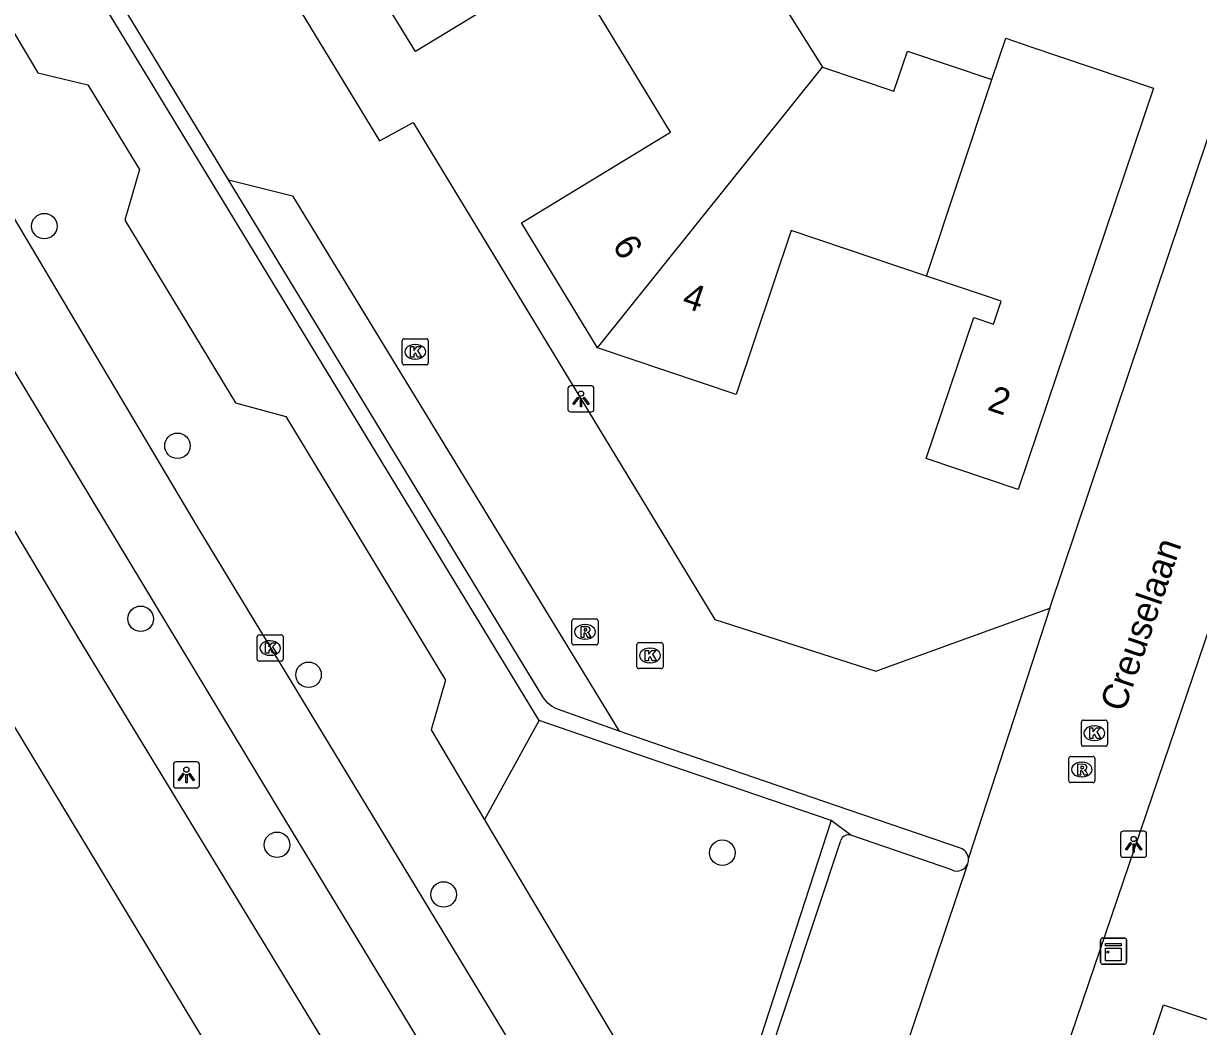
# Model space of a CAD drawing. Extents: x 157767 to 159171, y 387842 to 389425.
# Drawn here: x 158155.67 to 158200.72, y 388302.87 to 388341.31 of the extents above; entities that cross this region are included whole.
import ezdxf

# ---------------------------------------------------------------- set-up
doc = ezdxf.new("R2010")
doc.units = 0
for name, color, linetype in [('IMGEO_Boom', 7, 'Continuous'), ('IMGEO_Fietspad_gesloten', 7, 'Continuous'), ('IMGEO_Groenvoorziening', 7, 'Continuous'), ('IMGEO_Kast', 7, 'Continuous'), ('IMGEO_Kolk', 7, 'Continuous'), ('IMGEO_Lichtpunt', 7, 'Continuous'), ('IMGEO_Muur', 7, 'Continuous'), ('IMGEO_Openbare_ruimte_label', 7, 'Continuous'), ('IMGEO_Pand', 7, 'Continuous'), ('IMGEO_Pand_nummerreeks', 7, 'Continuous'), ('IMGEO_Rijbaan_lokaal_open', 7, 'Continuous'), ('IMGEO_Rijbaan_regionaal_gesloten', 7, 'Continuous'), ('IMGEO_Rioolput', 7, 'Continuous'), ('IMGEO_Voetpad_open', 7, 'Continuous')]:
    doc.layers.add(name, color=color, linetype=linetype)

msp = doc.modelspace()

# ---------------------------------------------------------------- linework, layer by layer
at = {"layer": 'IMGEO_Boom'}
for centre in [(158156.47, 388333.544), (158161.572, 388325.124), (158160.162, 388318.494), (158166.599, 388316.349), (158165.391, 388309.834), (158182.464, 388309.529), (158171.777, 388307.929)]:
    msp.add_circle(centre, 0.489, dxfattribs=at)
at = {"layer": 'IMGEO_Fietspad_gesloten'}
for points in [[(158134.936, 388368.569), (158152.031, 388339.346), (158162.359, 388321.986), (158175.742, 388299.912), (158188.418, 388279.263), (158195.13, 388268.765)], [(158178.868, 388289.086), (158165.181, 388311.658), (158153.286, 388331.356), (158142.759, 388349.282), (158132.45, 388366.885)]]:
    msp.add_lwpolyline(points, dxfattribs=at)
at = {"layer": 'IMGEO_Groenvoorziening'}
for points in [[(158133.376, 388377.573), (158139.588, 388367.158), (158141.543, 388366.666), (158143.57, 388363.424), (158142.99, 388361.495), (158145.126, 388357.922), (158147.067, 388357.45), (158149.128, 388354.196), (158148.513, 388352.268), (158150.628, 388348.658), (158152.625, 388348.163), (158154.628, 388344.956), (158154.075, 388343.02), (158156.218, 388339.413), (158158.137, 388338.952), (158160.119, 388335.714), (158159.551, 388333.769), (158163.802, 388326.774), (158165.73, 388326.242), (158171.855, 388316.141), (158171.296, 388314.237), (158173.351, 388310.787)], [(158173.351, 388310.787), (158175.446, 388314.592)], [(158173.351, 388310.787), (158183.658, 388293.483), (158185.543, 388292.972), (158189.658, 388286.335), (158189.095, 388284.416), (158195.332, 388273.955), (158197.254, 388273.407), (158198.647, 388271.084)]]:
    msp.add_lwpolyline(points, dxfattribs=at)
at = {"layer": 'IMGEO_Kast'}
for p, q in [((158197.037, 388306.26), (158197.878, 388306.26)), ((158197.878, 388306.26), (158197.037, 388306.26)), ((158196.962, 388305.335), (158196.962, 388306.176)), ((158196.962, 388306.176), (158196.962, 388305.335)), ((158197.962, 388306.185), (158197.962, 388305.344)), ((158197.962, 388305.344), (158197.962, 388306.185)), ((158197.887, 388305.26), (158197.046, 388305.26)), ((158197.046, 388305.26), (158197.887, 388305.26))]:
    msp.add_line(p, q, dxfattribs=at)
for points in [[(158197.157, 388306.05), (158197.757, 388306.05), (158197.757, 388305.965), (158197.157, 388305.965), (158197.157, 388306.05)], [(158197.157, 388305.875), (158197.757, 388305.875), (158197.757, 388305.386), (158197.157, 388305.386), (158197.157, 388305.875)]]:
    msp.add_lwpolyline(points, dxfattribs=at)
msp.add_circle((158197.241, 388305.724), 0.0377, dxfattribs=at)
for centre, start, end in [((158197.04, 388306.182), 92.4484, 184.2845), ((158197.04, 388306.182), 92.4484, 184.2845), ((158197.884, 388306.182), 2.4484, 94.2845), ((158197.884, 388306.182), 2.4484, 94.2845), ((158197.04, 388305.338), 182.4484, 274.2845), ((158197.04, 388305.338), 182.4484, 274.2845), ((158197.884, 388305.338), 272.4484, 4.2845), ((158197.884, 388305.338), 272.4484, 4.2845)]:
    msp.add_arc(centre, 0.0779, start, end, dxfattribs=at)
at = {"layer": 'IMGEO_Kolk'}
for p, q in [((158170.263, 388329.225), (158171.115, 388329.225)), ((158170.188, 388328.299), (158170.188, 388329.151)), ((158170.676, 388329.005), (158170.701, 388329.005)), ((158171.189, 388329.151), (158171.189, 388328.299)), ((158170.699, 388328.445), (158170.674, 388328.445)), ((158171.115, 388328.225), (158170.263, 388328.225)), ((158164.626, 388316.948), (158164.626, 388317.8)), ((158164.701, 388317.874), (158165.553, 388317.874)), ((158165.114, 388317.654), (158165.139, 388317.654)), ((158165.627, 388317.8), (158165.627, 388316.948)), ((158179.19, 388316.658), (158179.19, 388317.51)), ((158179.265, 388317.584), (158180.117, 388317.584)), ((158180.191, 388317.51), (158180.191, 388316.658)), ((158165.137, 388317.094), (158165.112, 388317.094)), ((158179.678, 388317.364), (158179.703, 388317.364)), ((158165.553, 388316.874), (158164.701, 388316.874)), ((158180.117, 388316.584), (158179.265, 388316.584)), ((158179.701, 388316.804), (158179.676, 388316.804)), ((158196.229, 388313.684), (158196.229, 388314.536)), ((158196.304, 388314.61), (158197.156, 388314.61)), ((158196.717, 388314.39), (158196.742, 388314.39)), ((158197.23, 388314.536), (158197.23, 388313.684)), ((158197.156, 388313.61), (158196.304, 388313.61)), ((158196.74, 388313.83), (158196.715, 388313.83))]:
    msp.add_line(p, q, dxfattribs=at)
for points in [[(158170.263, 388329.225), (158171.115, 388329.225)], [(158170.188, 388328.299), (158170.188, 388329.151)], [(158170.509, 388328.925), (158170.632, 388328.925), (158170.632, 388328.774), (158170.762, 388328.925), (158170.926, 388328.925), (158170.78, 388328.774), (158170.933, 388328.525), (158170.781, 388328.525), (158170.696, 388328.689), (158170.632, 388328.622), (158170.632, 388328.525), (158170.509, 388328.525), (158170.509, 388328.925)], [(158171.189, 388329.151), (158171.189, 388328.299)], [(158171.115, 388328.225), (158170.263, 388328.225)], [(158164.626, 388316.948), (158164.626, 388317.8)], [(158164.701, 388317.874), (158165.553, 388317.874)], [(158164.947, 388317.574), (158165.07, 388317.574), (158165.07, 388317.423), (158165.2, 388317.574), (158165.364, 388317.574), (158165.218, 388317.423), (158165.371, 388317.174), (158165.219, 388317.174), (158165.134, 388317.338), (158165.07, 388317.271), (158165.07, 388317.174), (158164.947, 388317.174), (158164.947, 388317.574)], [(158165.627, 388317.8), (158165.627, 388316.948)], [(158179.19, 388316.658), (158179.19, 388317.51)], [(158179.265, 388317.584), (158180.117, 388317.584)], [(158180.191, 388317.51), (158180.191, 388316.658)], [(158179.511, 388317.284), (158179.634, 388317.284), (158179.634, 388317.133), (158179.764, 388317.284), (158179.928, 388317.284), (158179.782, 388317.133), (158179.935, 388316.884), (158179.783, 388316.884), (158179.698, 388317.048), (158179.634, 388316.981), (158179.634, 388316.884), (158179.511, 388316.884), (158179.511, 388317.284)], [(158165.553, 388316.874), (158164.701, 388316.874)], [(158180.117, 388316.584), (158179.265, 388316.584)], [(158196.229, 388313.684), (158196.229, 388314.536)], [(158196.304, 388314.61), (158197.156, 388314.61)], [(158197.23, 388314.536), (158197.23, 388313.684)], [(158196.55, 388314.31), (158196.673, 388314.31), (158196.673, 388314.159), (158196.803, 388314.31), (158196.967, 388314.31), (158196.821, 388314.159), (158196.974, 388313.91), (158196.822, 388313.91), (158196.737, 388314.074), (158196.673, 388314.007), (158196.673, 388313.91), (158196.55, 388313.91), (158196.55, 388314.31)], [(158197.156, 388313.61), (158196.304, 388313.61)]]:
    msp.add_lwpolyline(points, dxfattribs=at)
for centre, start, end in [((158170.265, 388329.149), 91.552, 178.448), ((158170.265, 388329.149), 91.552, 178.448), ((158171.113, 388329.149), 1.552, 88.448), ((158171.113, 388329.149), 1.552, 88.448), ((158170.265, 388328.301), 181.552, 268.448), ((158170.265, 388328.301), 181.552, 268.448), ((158171.113, 388328.301), 271.552, 358.448), ((158171.113, 388328.301), 271.552, 358.448), ((158164.703, 388317.798), 91.552, 178.448), ((158164.703, 388317.798), 91.552, 178.448), ((158165.551, 388317.798), 1.552, 88.448), ((158165.551, 388317.798), 1.552, 88.448), ((158179.267, 388317.508), 91.552, 178.448), ((158179.267, 388317.508), 91.552, 178.448), ((158180.115, 388317.508), 1.552, 88.448), ((158180.115, 388317.508), 1.552, 88.448), ((158164.703, 388316.95), 181.552, 268.448), ((158164.703, 388316.95), 181.552, 268.448), ((158165.551, 388316.95), 271.552, 358.448), ((158165.551, 388316.95), 271.552, 358.448), ((158179.267, 388316.66), 181.552, 268.448), ((158179.267, 388316.66), 181.552, 268.448), ((158180.115, 388316.66), 271.552, 358.448), ((158180.115, 388316.66), 271.552, 358.448), ((158196.306, 388314.534), 91.552, 178.448), ((158196.306, 388314.534), 91.552, 178.448), ((158197.154, 388314.534), 1.552, 88.448), ((158197.154, 388314.534), 1.552, 88.448), ((158196.306, 388313.686), 181.552, 268.448), ((158196.306, 388313.686), 181.552, 268.448), ((158197.154, 388313.686), 271.552, 358.448), ((158197.154, 388313.686), 271.552, 358.448)]:
    msp.add_arc(centre, 0.0765, start, end, dxfattribs=at)
for centre, major_axis, ratio, start_param, end_param in [((158170.675, 388328.725), (-0.387, 0.002), 0.722429, 4.712389, 7.853982), ((158170.7, 388328.725), (-0.39, 0.002), 0.717154, 1.570796, 4.712389), ((158165.113, 388317.374), (-0.387, 0.002), 0.722429, 4.712389, 7.853982), ((158165.138, 388317.374), (-0.39, 0.002), 0.717154, 1.570796, 4.712389), ((158179.677, 388317.084), (-0.387, 0.002), 0.722429, 4.712389, 7.853982), ((158179.702, 388317.084), (-0.39, 0.002), 0.717154, 1.570796, 4.712389), ((158196.716, 388314.11), (-0.387, 0.002), 0.722429, 4.712389, 7.853982), ((158196.741, 388314.11), (-0.39, 0.002), 0.717154, 1.570796, 4.712389)]:
    msp.add_ellipse(centre, major_axis=major_axis, ratio=ratio, start_param=start_param, end_param=end_param, dxfattribs=at)
at = {"layer": 'IMGEO_Lichtpunt'}
for p, q in [((158177.448, 388327.422), (158176.64, 388327.422)), ((158177.448, 388327.422), (158176.64, 388327.422)), ((158176.546, 388327.327), (158176.546, 388326.52)), ((158176.546, 388327.327), (158176.546, 388326.52)), ((158177.542, 388326.52), (158177.542, 388327.327)), ((158177.542, 388326.52), (158177.542, 388327.327)), ((158176.64, 388326.426), (158177.448, 388326.426)), ((158176.64, 388326.426), (158177.448, 388326.426)), ((158162.318, 388313.01), (158161.51, 388313.01)), ((158162.318, 388313.01), (158161.51, 388313.01)), ((158161.416, 388312.915), (158161.416, 388312.108)), ((158161.416, 388312.915), (158161.416, 388312.108)), ((158162.412, 388312.108), (158162.412, 388312.915)), ((158162.412, 388312.108), (158162.412, 388312.915)), ((158161.51, 388312.014), (158162.318, 388312.014)), ((158161.51, 388312.014), (158162.318, 388312.014)), ((158198.635, 388310.352), (158197.827, 388310.352)), ((158198.635, 388310.352), (158197.827, 388310.352)), ((158197.733, 388310.257), (158197.733, 388309.45)), ((158197.733, 388310.257), (158197.733, 388309.45)), ((158198.729, 388309.45), (158198.729, 388310.257)), ((158198.729, 388309.45), (158198.729, 388310.257)), ((158197.827, 388309.356), (158198.635, 388309.356)), ((158197.827, 388309.356), (158198.635, 388309.356))]:
    msp.add_line(p, q, dxfattribs=at)
for points in [[(158176.92, 388326.991), (158176.959, 388326.963), (158176.771, 388326.701), (158176.733, 388326.728), (158176.92, 388326.991)], [(158177.022, 388326.943), (158177.069, 388326.943), (158177.069, 388326.621), (158177.022, 388326.621), (158177.022, 388326.943)], [(158177.132, 388326.963), (158177.17, 388326.99), (158177.357, 388326.728), (158177.318, 388326.7), (158177.132, 388326.963)], [(158161.79, 388312.579), (158161.829, 388312.551), (158161.641, 388312.289), (158161.603, 388312.316), (158161.79, 388312.579)], [(158161.892, 388312.531), (158161.939, 388312.531), (158161.939, 388312.209), (158161.892, 388312.209), (158161.892, 388312.531)], [(158162.002, 388312.551), (158162.04, 388312.578), (158162.227, 388312.316), (158162.188, 388312.288), (158162.002, 388312.551)], [(158198.107, 388309.921), (158198.146, 388309.893), (158197.958, 388309.631), (158197.92, 388309.658), (158198.107, 388309.921)], [(158198.209, 388309.873), (158198.256, 388309.873), (158198.256, 388309.551), (158198.209, 388309.551), (158198.209, 388309.873)], [(158198.319, 388309.893), (158198.357, 388309.92), (158198.544, 388309.658), (158198.505, 388309.63), (158198.319, 388309.893)]]:
    msp.add_lwpolyline(points, dxfattribs=at)
for centre in [(158177.045, 388327.125), (158161.915, 388312.713), (158198.232, 388310.055)]:
    msp.add_circle(centre, 0.0994, dxfattribs=at)
for centre, start, end in [((158176.64, 388327.327), 90, 180), ((158176.64, 388327.327), 90, 180), ((158177.448, 388327.327), 0, 90), ((158177.448, 388327.327), 0, 90), ((158176.64, 388326.52), 180, 270), ((158176.64, 388326.52), 180, 270), ((158177.448, 388326.52), 270, 0), ((158177.448, 388326.52), 270, 360), ((158161.51, 388312.915), 90, 180), ((158161.51, 388312.915), 90, 180), ((158162.318, 388312.915), 0, 90), ((158162.318, 388312.915), 0, 90), ((158161.51, 388312.108), 180, 270), ((158161.51, 388312.108), 180, 270), ((158162.318, 388312.108), 270, 0), ((158162.318, 388312.108), 270, 360), ((158197.827, 388310.257), 90, 180), ((158197.827, 388310.257), 90, 180), ((158198.635, 388310.257), 0, 90), ((158198.635, 388310.257), 0, 90), ((158197.827, 388309.45), 180, 270), ((158197.827, 388309.45), 180, 270), ((158198.635, 388309.45), 270, 0), ((158198.635, 388309.45), 270, 360)]:
    msp.add_arc(centre, 0.0946, start, end, dxfattribs=at)
at = {"layer": 'IMGEO_Muur'}
for points in [[(158133.376, 388377.573), (158139.588, 388367.158), (158141.543, 388366.666), (158143.57, 388363.424), (158142.99, 388361.495), (158145.126, 388357.922), (158147.067, 388357.45), (158149.128, 388354.196), (158148.513, 388352.268), (158150.628, 388348.658), (158152.625, 388348.163), (158154.628, 388344.956), (158154.075, 388343.02), (158156.218, 388339.413), (158158.137, 388338.952), (158160.119, 388335.714), (158159.551, 388333.769), (158163.802, 388326.774), (158165.73, 388326.242), (158171.855, 388316.141), (158171.296, 388314.237), (158173.351, 388310.787)], [(158173.351, 388310.787), (158183.658, 388293.483), (158185.543, 388292.972), (158189.658, 388286.335), (158189.095, 388284.416), (158195.332, 388273.955), (158197.254, 388273.407)]]:
    msp.add_lwpolyline(points, dxfattribs=at)
at = {"layer": 'IMGEO_Pand'}
for points in [[(158184.407, 388346.024), (158186.251, 388342.998), (158184.762, 388342.091), (158186.307, 388339.632)], [(158177.596, 388341.876), (158176.458, 388343.744), (158176.041, 388344.428), (158175.151, 388343.885), (158175.567, 388343.201), (158170.699, 388340.235), (158168.953, 388343.1)], [(158177.671, 388328.884), (158174.758, 388333.664), (158180.477, 388337.149), (158177.596, 388341.876)], [(158192.798, 388339.156), (158193.331, 388340.74), (158194.256, 388340.428), (158198.994, 388338.831), (158193.806, 388323.444), (158190.28, 388324.633), (158192.101, 388330.035), (158192.86, 388329.78), (158193.158, 388330.663), (158192.399, 388330.919), (158190.296, 388331.628)], [(158186.307, 388339.632), (158189.043, 388338.71), (158189.561, 388340.247), (158192.798, 388339.156)], [(158177.671, 388328.884), (158186.307, 388339.632)], [(158190.296, 388331.628), (158192.798, 388339.156)], [(158190.296, 388331.628), (158185.107, 388333.378), (158182.988, 388327.092), (158177.671, 388328.884)], [(158197.134, 388296.971), (158199.379, 388303.704), (158205.746, 388301.581), (158207.479, 388306.778)]]:
    msp.add_lwpolyline(points, dxfattribs=at)
at = {"layer": 'IMGEO_Rijbaan_lokaal_open'}
for points in [[(158180.797, 388442.173), (158153.056, 388425.158), (158153.984, 388423.292), (158141.098, 388415.471), (158135.994, 388394.364), (158144.897, 388379.594), (158143.742, 388378.793), (158169.317, 388336.817), (158170.612, 388337.516), (158182.172, 388318.47), (158188.347, 388316.482), (158195.026, 388318.901)], [(158163.532, 388335.322), (158139.968, 388374.072)], [(158195.026, 388318.901), (158203.621, 388344.484)], [(158207.176, 388335.906), (158193.823, 388296.623), (158193.889, 388296.514)], [(158163.532, 388335.322), (158165.985, 388334.699), (158178.511, 388314.19)], [(158195.026, 388318.901), (158191.9, 388309.316)], [(158191.591, 388309.706), (158186.808, 388311.343), (158180.125, 388313.63), (158178.511, 388314.19)], [(158188.099, 388297.872), (158191.87, 388309.106)]]:
    msp.add_lwpolyline(points, dxfattribs=at)
for centre, radius, start, end in [((158191.449, 388309.276), 0.453, 5.0606, 71.7195), ((158191.468, 388309.271), 0.434, 337.7327, 6.0071)]:
    msp.add_arc(centre, radius, start, end, dxfattribs=at)
at = {"layer": 'IMGEO_Rijbaan_regionaal_gesloten'}
for points in [[(158200.59, 388240.362), (158192.107, 388254.146), (158166.877, 388295.262), (158150.236, 388322.758), (158131.842, 388353.83), (158117.262, 388378.952), (158097.857, 388412.932), (158070.009, 388461.63), (158044.126, 388506.669), (158040.061, 388513.776), (158019.492, 388549.641), (158005.756, 388573.613)], [(158178.959, 388283.153), (158173.795, 388291.448), (158157.789, 388317.741), (158139.769, 388348), (158129.845, 388365.121)]]:
    msp.add_lwpolyline(points, dxfattribs=at)
at = {"layer": 'IMGEO_Rioolput'}
for p, q in [((158176.699, 388317.566), (158176.699, 388318.418)), ((158176.774, 388318.492), (158177.626, 388318.492)), ((158177.7, 388318.418), (158177.7, 388317.566)), ((158177.187, 388318.272), (158177.212, 388318.272)), ((158177.626, 388317.492), (158176.774, 388317.492)), ((158177.21, 388317.712), (158177.185, 388317.712)), ((158195.746, 388312.291), (158195.746, 388313.143)), ((158195.821, 388313.217), (158196.673, 388313.217)), ((158196.234, 388312.997), (158196.259, 388312.997)), ((158196.747, 388313.143), (158196.747, 388312.291)), ((158196.673, 388312.217), (158195.821, 388312.217)), ((158196.257, 388312.437), (158196.232, 388312.437))]:
    msp.add_line(p, q, dxfattribs=at)
for points in [[(158176.699, 388317.566), (158176.699, 388318.418)], [(158176.774, 388318.492), (158177.626, 388318.492)], [(158177.7, 388318.418), (158177.7, 388317.566)], [(158177.288, 388318.19), (158177.036, 388318.192), (158177.036, 388317.792)], [(158177.036, 388317.792), (158177.16, 388317.792), (158177.16, 388317.954), (158177.171, 388317.954)], [(158177.214, 388318.111), (158177.16, 388318.111), (158177.16, 388318.03)], [(158177.16, 388318.03), (158177.212, 388318.03)], [(158177.626, 388317.492), (158176.774, 388317.492)], [(158177.218, 388317.925), (158177.289, 388317.792), (158177.429, 388317.792), (158177.364, 388317.918)], [(158195.746, 388312.291), (158195.746, 388313.143)], [(158195.821, 388313.217), (158196.673, 388313.217)], [(158196.747, 388313.143), (158196.747, 388312.291)], [(158196.335, 388312.915), (158196.083, 388312.917), (158196.083, 388312.517)], [(158196.083, 388312.517), (158196.207, 388312.517), (158196.207, 388312.679), (158196.218, 388312.679)], [(158196.261, 388312.836), (158196.207, 388312.836), (158196.207, 388312.755)], [(158196.207, 388312.755), (158196.259, 388312.755)], [(158196.265, 388312.65), (158196.336, 388312.517), (158196.476, 388312.517), (158196.411, 388312.643)], [(158196.673, 388312.217), (158195.821, 388312.217)]]:
    msp.add_lwpolyline(points, dxfattribs=at)
for centre, radius, start, end in [((158176.776, 388318.416), 0.0765, 91.552, 178.448), ((158176.776, 388318.416), 0.0765, 91.552, 178.448), ((158177.624, 388318.416), 0.0765, 1.552, 88.448), ((158177.624, 388318.416), 0.0765, 1.552, 88.448), ((158177.17, 388317.901), 0.0533, 26.0293, 88.6989), ((158177.196, 388318.219), 0.19, 274.7715, 282.9687), ((158177.22, 388318.015), 0.0964, 77.0061, 93.1865), ((158177.234, 388318.072), 0.0378, 276.6634, 79.6772), ((158177.287, 388318.08), 0.109, 350.3612, 89.416), ((158177.285, 388318.08), 0.112, 277.5842, 350.9817), ((158177.269, 388317.865), 0.108, 29.5134, 73.7905), ((158176.776, 388317.568), 0.0765, 181.552, 268.448), ((158176.776, 388317.568), 0.0765, 181.552, 268.448), ((158177.624, 388317.568), 0.0765, 271.552, 358.448), ((158177.624, 388317.568), 0.0765, 271.552, 358.448), ((158195.823, 388313.141), 0.0765, 91.552, 178.448), ((158195.823, 388313.141), 0.0765, 91.552, 178.448), ((158196.671, 388313.141), 0.0765, 1.552, 88.448), ((158196.671, 388313.141), 0.0765, 1.552, 88.448), ((158196.217, 388312.626), 0.0533, 26.0293, 88.6989), ((158196.243, 388312.944), 0.19, 274.7715, 282.9687), ((158196.267, 388312.74), 0.0964, 77.0061, 93.1865), ((158196.281, 388312.797), 0.0378, 276.6634, 79.6772), ((158196.334, 388312.805), 0.109, 350.3612, 89.416), ((158196.332, 388312.805), 0.112, 277.5842, 350.9817), ((158196.316, 388312.59), 0.108, 29.5134, 73.7905), ((158195.823, 388312.293), 0.0765, 181.552, 268.448), ((158195.823, 388312.293), 0.0765, 181.552, 268.448), ((158196.671, 388312.293), 0.0765, 271.552, 358.448), ((158196.671, 388312.293), 0.0765, 271.552, 358.448)]:
    msp.add_arc(centre, radius, start, end, dxfattribs=at)
for centre, major_axis, ratio, start_param, end_param in [((158177.186, 388317.992), (-0.387, 0.002), 0.722429, 4.712389, 7.853982), ((158177.211, 388317.992), (-0.39, 0.002), 0.717154, 1.570796, 4.712389), ((158196.233, 388312.717), (-0.387, 0.002), 0.722429, 4.712389, 7.853982), ((158196.258, 388312.717), (-0.39, 0.002), 0.717154, 1.570796, 4.712389)]:
    msp.add_ellipse(centre, major_axis=major_axis, ratio=ratio, start_param=start_param, end_param=end_param, dxfattribs=at)
at = {"layer": 'IMGEO_Voetpad_open'}
for points in [[(158175.446, 388314.592), (158129.494, 388390.09), (158131.254, 388397.124)], [(158178.511, 388314.19), (158176.182, 388315.018), (158176.119, 388315.042), (158176.026, 388315.087), (158175.938, 388315.139), (158175.854, 388315.199), (158175.776, 388315.266), (158175.705, 388315.34), (158175.64, 388315.42), (158175.583, 388315.505), (158163.532, 388335.322)], [(158186.634, 388310.76), (158179.922, 388313.047), (158175.446, 388314.592)], [(158186.634, 388310.76), (158183.422, 388300.898), (158183.553, 388299.72), (158204.079, 388265.917), (158226.561, 388260.197), (158227.06, 388260.07)], [(158187.395, 388310.197), (158186.634, 388310.76)], [(158184.081, 388301.187), (158187.003, 388310.002)], [(158191.263, 388308.871), (158187.395, 388310.197)]]:
    msp.add_lwpolyline(points, dxfattribs=at)
for centre, radius, start, end in [((158187.296, 388309.905), 0.308, 71.2002, 161.6958), ((158191.455, 388309.276), 0.448, 244.6326, 337.6952)]:
    msp.add_arc(centre, radius, start, end, dxfattribs=at)

# ---------------------------------------------------------------- texts
at = {"layer": 'IMGEO_Openbare_ruimte_label'}
msp.add_text('Creuselaan', height=1, rotation=71.1667, dxfattribs=at).set_placement((158197.87, 388314.882))
at = {"layer": 'IMGEO_Pand_nummerreeks'}
for s, rotation, p in [('6', 301.3463, (158178.222, 388332.82)), ('4', 341.3714, (158180.873, 388330.464)), ('2', 341.3654, (158192.586, 388326.514))]:
    msp.add_text(s, height=1, rotation=rotation, dxfattribs=at).set_placement(p)

doc.saveas('drawing.dxf')
